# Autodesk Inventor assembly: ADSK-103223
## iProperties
Shininess: 0.0
Created: 2000-11
Part Number: ADSK-103223
Document SubType Name: Assembly
Stock Number: ADSK-103223
Density: 0.0
Volumn: 0.0
Area: 0.0
PropertySet Name: Model Information
Control State: 0
Master: False
Checked Out: False
Author: gao
